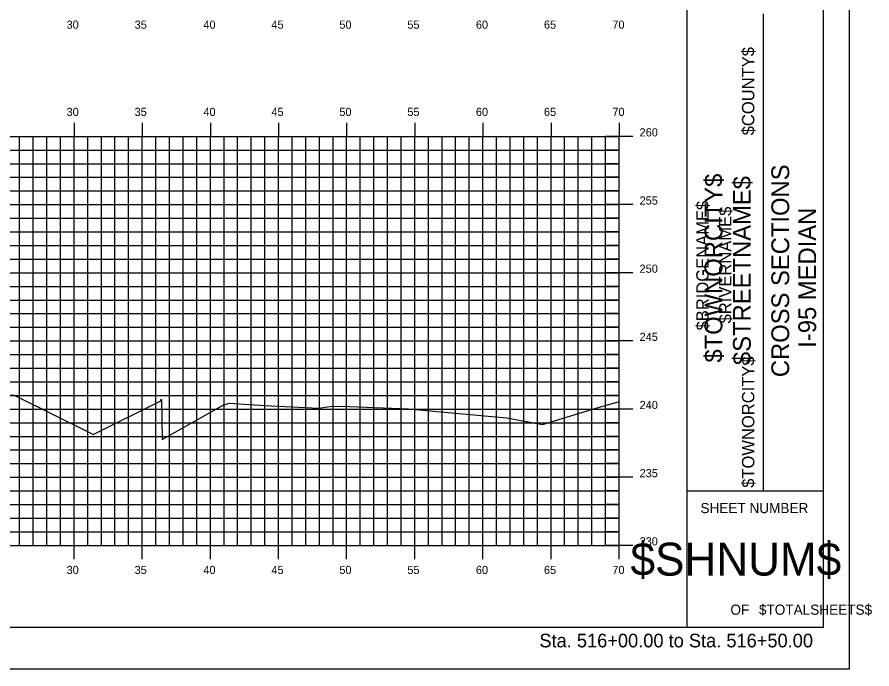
# Model space of a CAD drawing. Extents: x 1168600 to 1177589, y 610178 to 611246.
# Drawn here: x 1173756.9 to 1173819.6, y 610268.7 to 610316.6 of the extents above; entities that cross this region are included whole.
import ezdxf

# ---------------------------------------------------------------- set-up
doc = ezdxf.new("R2010")
doc.units = 0
for name, color, linetype in [('_Station Equation', 7, 'Continuous'), ('BORDER', 7, 'Continuous'), ('BRIDGE_TITLE', 7, 'Continuous'), ('H_V ANNOTATION', 7, 'Continuous'), ('HIGHWAY_TITLE', 7, 'Continuous'), ('MAJOR', 7, 'Continuous'), ('MINOR', 7, 'Continuous'), ('PLOT BOUNDARY', 7, 'Continuous')]:
    doc.layers.add(name, color=color, linetype=linetype)

msp = doc.modelspace()

# ---------------------------------------------------------------- linework, layer by layer
at = {"layer": '_Station Equation'}
msp.add_lwpolyline([(1173752.352, 610288.923), (1173753.638, 610288.874), (1173753.751, 610288.872), (1173756.654, 610288.819), (1173756.815, 610288.739), (1173762.24, 610286.05), (1173762.46, 610285.941), (1173767.418, 610288.395), (1173767.429, 610288.492), (1173767.441, 610288.512), (1173767.468, 610288.512), (1173767.535, 610285.559), (1173771.558, 610287.855), (1173772.002, 610288.076), (1173772.436, 610288.226), (1173775.028, 610288.052), (1173779.007, 610287.872), (1173779.838, 610288.002), (1173780.661, 610288.023), (1173785.576, 610287.823), (1173792.789, 610287.15), (1173795.426, 610286.673), (1173799.272, 610287.833), (1173801.063, 610288.357)], dxfattribs=at)
at = {"layer": 'BORDER'}
for p, q in [((1173806.063, 610271.804), (1173806.063, 610376.804)), ((1173816.063, 610271.804), (1173816.063, 610376.804)), ((1173811.654, 610281.804), (1173811.654, 610316.804)), ((1173806.063, 610281.804), (1173816.063, 610281.804)), ((1173656.063, 610271.801), (1173816.063, 610271.801))]:
    msp.add_line(p, q, dxfattribs=at)
at = {"layer": 'MAJOR'}
for p, q in [((1173761.063, 610308.803), (1173761.063, 610307.801)), ((1173766.063, 610308.803), (1173766.063, 610307.801)), ((1173771.063, 610308.803), (1173771.063, 610307.801)), ((1173776.063, 610308.803), (1173776.063, 610307.801)), ((1173781.063, 610308.803), (1173781.063, 610307.801)), ((1173786.063, 610308.803), (1173786.063, 610307.801)), ((1173791.063, 610308.803), (1173791.063, 610307.801)), ((1173796.063, 610308.803), (1173796.063, 610307.801)), ((1173801.063, 610308.803), (1173801.063, 610307.801)), ((1173661.063, 610307.801), (1173801.063, 610307.801)), ((1173661.063, 610307.801), (1173801.063, 610307.801)), ((1173761.063, 610277.801), (1173761.063, 610307.801)), ((1173766.063, 610277.801), (1173766.063, 610307.801)), ((1173771.063, 610277.801), (1173771.063, 610307.801)), ((1173776.063, 610277.801), (1173776.063, 610307.801)), ((1173781.063, 610277.801), (1173781.063, 610307.801)), ((1173786.063, 610277.801), (1173786.063, 610307.801)), ((1173791.063, 610277.801), (1173791.063, 610307.801)), ((1173796.063, 610277.801), (1173796.063, 610307.801)), ((1173802.065, 610307.801), (1173800.061, 610307.801)), ((1173801.063, 610277.801), (1173801.063, 610307.801)), ((1173801.063, 610277.801), (1173801.063, 610307.801)), ((1173661.063, 610302.801), (1173801.063, 610302.801)), ((1173802.065, 610302.801), (1173800.061, 610302.801)), ((1173661.063, 610297.801), (1173801.063, 610297.801)), ((1173802.065, 610297.801), (1173800.061, 610297.801)), ((1173661.063, 610292.801), (1173801.063, 610292.801)), ((1173802.065, 610292.801), (1173800.061, 610292.801)), ((1173661.063, 610287.801), (1173801.063, 610287.801)), ((1173802.065, 610287.801), (1173800.061, 610287.801)), ((1173661.063, 610282.801), (1173801.063, 610282.801)), ((1173802.065, 610282.801), (1173800.061, 610282.801)), ((1173661.063, 610277.801), (1173801.063, 610277.801)), ((1173661.063, 610277.801), (1173801.063, 610277.801)), ((1173761.063, 610276.799), (1173761.063, 610277.801)), ((1173766.063, 610276.799), (1173766.063, 610277.801)), ((1173771.063, 610276.799), (1173771.063, 610277.801)), ((1173776.063, 610276.799), (1173776.063, 610277.801)), ((1173781.063, 610276.799), (1173781.063, 610277.801)), ((1173786.063, 610276.799), (1173786.063, 610277.801)), ((1173791.063, 610276.799), (1173791.063, 610277.801)), ((1173796.063, 610276.799), (1173796.063, 610277.801)), ((1173802.065, 610277.801), (1173800.061, 610277.801)), ((1173801.063, 610276.799), (1173801.063, 610277.801))]:
    msp.add_line(p, q, dxfattribs=at)
at = {"layer": 'MINOR'}
for p, q in [((1173757.063, 610277.801), (1173757.063, 610307.801)), ((1173758.063, 610277.801), (1173758.063, 610307.801)), ((1173759.063, 610277.801), (1173759.063, 610307.801)), ((1173760.063, 610277.801), (1173760.063, 610307.801)), ((1173762.063, 610277.801), (1173762.063, 610307.801)), ((1173763.063, 610277.801), (1173763.063, 610307.801)), ((1173764.063, 610277.801), (1173764.063, 610307.801)), ((1173765.063, 610277.801), (1173765.063, 610307.801)), ((1173767.063, 610277.801), (1173767.063, 610307.801)), ((1173768.063, 610277.801), (1173768.063, 610307.801)), ((1173769.063, 610277.801), (1173769.063, 610307.801)), ((1173770.063, 610277.801), (1173770.063, 610307.801)), ((1173772.063, 610277.801), (1173772.063, 610307.801)), ((1173773.063, 610277.801), (1173773.063, 610307.801)), ((1173774.063, 610277.801), (1173774.063, 610307.801)), ((1173775.063, 610277.801), (1173775.063, 610307.801)), ((1173777.063, 610277.801), (1173777.063, 610307.801)), ((1173778.063, 610277.801), (1173778.063, 610307.801)), ((1173779.063, 610277.801), (1173779.063, 610307.801)), ((1173780.063, 610277.801), (1173780.063, 610307.801)), ((1173782.063, 610277.801), (1173782.063, 610307.801)), ((1173783.063, 610277.801), (1173783.063, 610307.801)), ((1173784.063, 610277.801), (1173784.063, 610307.801)), ((1173785.063, 610277.801), (1173785.063, 610307.801)), ((1173787.063, 610277.801), (1173787.063, 610307.801)), ((1173788.063, 610277.801), (1173788.063, 610307.801)), ((1173789.063, 610277.801), (1173789.063, 610307.801)), ((1173790.063, 610277.801), (1173790.063, 610307.801)), ((1173792.063, 610277.801), (1173792.063, 610307.801)), ((1173793.063, 610277.801), (1173793.063, 610307.801)), ((1173794.063, 610277.801), (1173794.063, 610307.801)), ((1173795.063, 610277.801), (1173795.063, 610307.801)), ((1173797.063, 610277.801), (1173797.063, 610307.801)), ((1173798.063, 610277.801), (1173798.063, 610307.801)), ((1173799.063, 610277.801), (1173799.063, 610307.801)), ((1173800.063, 610277.801), (1173800.063, 610307.801)), ((1173661.063, 610306.801), (1173801.063, 610306.801)), ((1173801.063, 610306.801), (1173800.061, 610306.801)), ((1173661.063, 610305.801), (1173801.063, 610305.801)), ((1173801.063, 610305.801), (1173800.061, 610305.801)), ((1173661.063, 610304.801), (1173801.063, 610304.801)), ((1173801.063, 610304.801), (1173800.061, 610304.801)), ((1173661.063, 610303.801), (1173801.063, 610303.801)), ((1173801.063, 610303.801), (1173800.061, 610303.801)), ((1173661.063, 610301.801), (1173801.063, 610301.801)), ((1173801.063, 610301.801), (1173800.061, 610301.801)), ((1173661.063, 610300.801), (1173801.063, 610300.801)), ((1173801.063, 610300.801), (1173800.061, 610300.801)), ((1173661.063, 610299.801), (1173801.063, 610299.801)), ((1173801.063, 610299.801), (1173800.061, 610299.801)), ((1173661.063, 610298.801), (1173801.063, 610298.801)), ((1173801.063, 610298.801), (1173800.061, 610298.801)), ((1173661.063, 610296.801), (1173801.063, 610296.801)), ((1173801.063, 610296.801), (1173800.061, 610296.801)), ((1173661.063, 610295.801), (1173801.063, 610295.801)), ((1173801.063, 610295.801), (1173800.061, 610295.801)), ((1173661.063, 610294.801), (1173801.063, 610294.801)), ((1173801.063, 610294.801), (1173800.061, 610294.801)), ((1173661.063, 610293.801), (1173801.063, 610293.801)), ((1173801.063, 610293.801), (1173800.061, 610293.801)), ((1173661.063, 610291.801), (1173801.063, 610291.801)), ((1173801.063, 610291.801), (1173800.061, 610291.801)), ((1173661.063, 610290.801), (1173801.063, 610290.801)), ((1173801.063, 610290.801), (1173800.061, 610290.801)), ((1173661.063, 610289.801), (1173801.063, 610289.801)), ((1173801.063, 610289.801), (1173800.061, 610289.801)), ((1173661.063, 610288.801), (1173801.063, 610288.801)), ((1173801.063, 610288.801), (1173800.061, 610288.801)), ((1173661.063, 610286.801), (1173801.063, 610286.801)), ((1173801.063, 610286.801), (1173800.061, 610286.801)), ((1173661.063, 610285.801), (1173801.063, 610285.801)), ((1173801.063, 610285.801), (1173800.061, 610285.801)), ((1173661.063, 610284.801), (1173801.063, 610284.801)), ((1173801.063, 610284.801), (1173800.061, 610284.801)), ((1173661.063, 610283.801), (1173801.063, 610283.801)), ((1173801.063, 610283.801), (1173800.061, 610283.801)), ((1173661.063, 610281.801), (1173801.063, 610281.801)), ((1173801.063, 610281.801), (1173800.061, 610281.801)), ((1173661.063, 610280.801), (1173801.063, 610280.801)), ((1173801.063, 610280.801), (1173800.061, 610280.801)), ((1173661.063, 610279.801), (1173801.063, 610279.801)), ((1173801.063, 610279.801), (1173800.061, 610279.801)), ((1173661.063, 610278.801), (1173801.063, 610278.801)), ((1173801.063, 610278.801), (1173800.061, 610278.801))]:
    msp.add_line(p, q, dxfattribs=at)
at = {"layer": 'PLOT BOUNDARY'}
msp.add_lwpolyline([(1173647.97, 610268.742), (1173817.97, 610268.742), (1173817.97, 610378.742), (1173647.97, 610378.742)], close=True, dxfattribs=at)

# ---------------------------------------------------------------- texts
at = {"layer": 'BORDER'}
for s, height, rotation, p in [('CROSS SECTIONS', 1.30428, 90, (1173813.539, 610290.143)), ('I-95 MEDIAN', 1.30428, 90, (1173815.517, 610292.302)), ('SHEET NUMBER', 0.74527, 360, (1173807.028, 610280.168)), ('$SHNUM$', 2.4194, 360, (1173801.896, 610275.584)), ('OF', 0.7453, 360, (1173809.23, 610272.714)), ('$TOTALSHEETS$', 0.74527, 360, (1173811.32, 610272.714))]:
    msp.add_text(s, height=height, rotation=rotation, dxfattribs=at).set_placement(p)
at = {"layer": 'BRIDGE_TITLE'}
for s, height, p in [('$COUNTY$', 0.9072, (1173810.983, 610307.883)), ('$BRIDGENAME$', 0.90716, (1173807.629, 610293.572)), ('$RIVERNAME$', 0.90716, (1173809.306, 610294.087)), ('$TOWNORCITY$', 0.90716, (1173810.983, 610282.025))]:
    msp.add_text(s, height=height, rotation=90, dxfattribs=at).set_placement(p)
at = {"layer": 'H_V ANNOTATION'}
for s, height, p in [('30', 0.6, (1173760.512, 610315.701)), ('35', 0.6, (1173765.503, 610315.701)), ('40', 0.6, (1173770.549, 610315.701)), ('45', 0.6, (1173775.541, 610315.701)), ('50', 0.6, (1173780.527, 610315.701)), ('55', 0.6, (1173785.519, 610315.701)), ('60', 0.6, (1173790.549, 610315.701)), ('65', 0.6, (1173795.541, 610315.701)), ('70', 0.6, (1173800.565, 610315.701)), ('30', 0.6, (1173760.512, 610309.301)), ('35', 0.6, (1173765.503, 610309.301)), ('40', 0.6, (1173770.549, 610309.301)), ('45', 0.6, (1173775.541, 610309.301)), ('50', 0.6, (1173780.527, 610309.301)), ('55', 0.6, (1173785.519, 610309.301)), ('60', 0.6, (1173790.549, 610309.301)), ('65', 0.6, (1173795.541, 610309.301)), ('70', 0.6, (1173800.565, 610309.301)), ('260', 0.6, (1173802.563, 610307.801)), ('255', 0.6, (1173802.563, 610302.801)), ('250', 0.6, (1173802.563, 610297.801)), ('245', 0.6, (1173802.563, 610292.801)), ('240', 0.6, (1173802.563, 610287.801)), ('235', 0.6, (1173802.563, 610282.801)), ('230', 0.6, (1173802.563, 610277.801)), ('30', 0.6, (1173760.512, 610275.701)), ('35', 0.6, (1173765.503, 610275.701)), ('40', 0.6, (1173770.549, 610275.701)), ('45', 0.6, (1173775.541, 610275.701)), ('50', 0.6, (1173780.527, 610275.701)), ('55', 0.6, (1173785.519, 610275.701)), ('60', 0.6, (1173790.549, 610275.701)), ('65', 0.6, (1173795.541, 610275.701)), ('70', 0.6, (1173800.565, 610275.701)), ('Sta. 516+00.00 to Sta. 516+50.00', 1.0002, (1173795.209, 610270.321))]:
    msp.add_text(s, height=height, dxfattribs=at).set_placement(p)
at = {"layer": 'HIGHWAY_TITLE'}
for s, p in [('$TOWNORCITY$', (1173808.635, 610291.212)), ('$STREETNAME$', (1173810.722, 610291.032))]:
    msp.add_text(s, height=1.30428, rotation=90, dxfattribs=at).set_placement(p)

doc.saveas('drawing.dxf')
